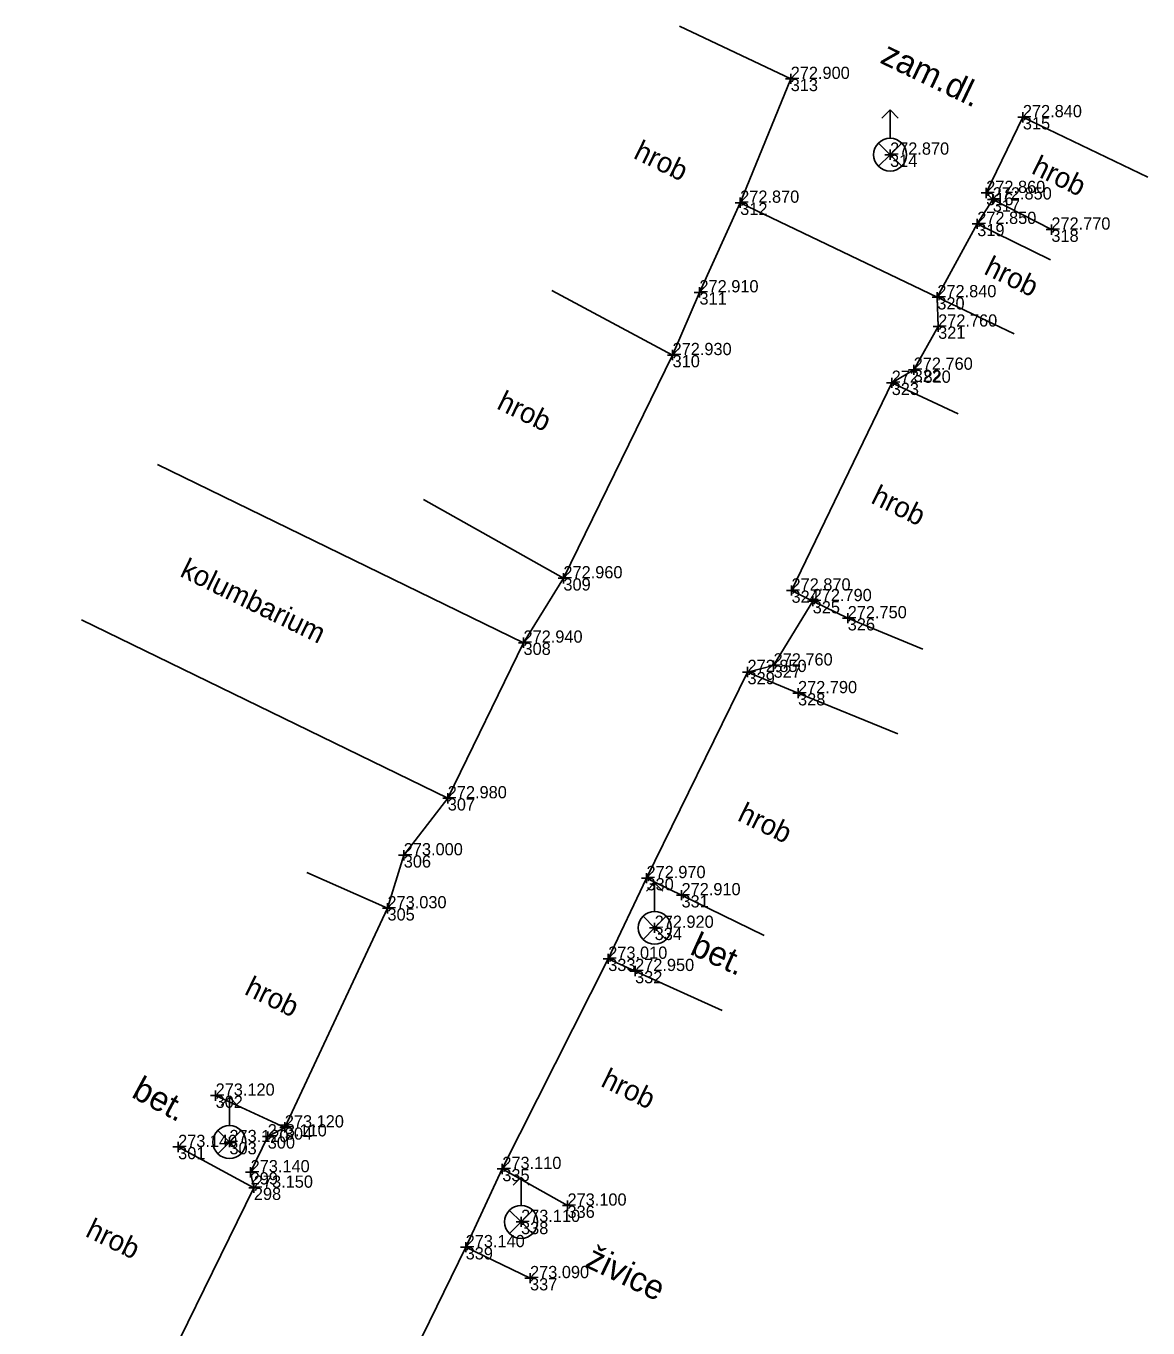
# Model space of a CAD drawing. Extents: x -776606 to -776076, y -974328 to -973875.
# Drawn here: x -776368.79 to -776355.01, y -974179.42 to -974163.44 of the extents above; entities that cross this region are included whole.
import ezdxf

# ---------------------------------------------------------------- set-up
doc = ezdxf.new("R2010")
doc.units = 0
for name, color, linetype in [('Body polohopisu', 7, 'Continuous'), ('Doplňkové značky', 7, 'Continuous'), ('Doplňující texty', 7, 'Continuous'), ('Ploty_opěrné zdi', 7, 'Continuous'), ('Rozhraní ploch', 7, 'Continuous'), ('Výšky bodů', 7, 'Continuous'), ('Čísla bodů', 7, 'Continuous')]:
    doc.layers.add(name, color=color, linetype=linetype)

msp = doc.modelspace()

# ---------------------------------------------------------------- linework, layer by layer
at = {"layer": 'Body polohopisu'}
for p, q in [((-776359.4, -974164.09), (-776359.4, -974164.027)), ((-776359.4, -974164.09), (-776359.463, -974164.09)), ((-776359.4, -974164.09), (-776359.338, -974164.09)), ((-776359.4, -974164.09), (-776359.4, -974164.152)), ((-776356.55, -974164.56), (-776356.55, -974164.498)), ((-776356.55, -974164.56), (-776356.613, -974164.56)), ((-776356.55, -974164.56), (-776356.488, -974164.56)), ((-776356.55, -974164.56), (-776356.55, -974164.623)), ((-776358.18, -974165.02), (-776358.18, -974164.958)), ((-776358.18, -974165.02), (-776358.243, -974165.02)), ((-776358.18, -974165.02), (-776358.118, -974165.02)), ((-776358.18, -974165.02), (-776358.18, -974165.083)), ((-776357, -974165.49), (-776357, -974165.427)), ((-776360.02, -974165.61), (-776360.083, -974165.61)), ((-776360.02, -974165.61), (-776360.02, -974165.547)), ((-776360.02, -974165.61), (-776359.958, -974165.61)), ((-776360.02, -974165.61), (-776360.02, -974165.672)), ((-776357, -974165.49), (-776357.062, -974165.49)), ((-776357, -974165.49), (-776356.938, -974165.49)), ((-776357, -974165.49), (-776357, -974165.552)), ((-776356.92, -974165.57), (-776356.983, -974165.57)), ((-776356.92, -974165.57), (-776356.92, -974165.508)), ((-776356.92, -974165.57), (-776356.858, -974165.57)), ((-776356.92, -974165.57), (-776356.92, -974165.633)), ((-776357.11, -974165.87), (-776357.172, -974165.87)), ((-776357.11, -974165.87), (-776357.11, -974165.807)), ((-776357.11, -974165.87), (-776357.047, -974165.87)), ((-776357.11, -974165.87), (-776357.11, -974165.932)), ((-776356.2, -974165.94), (-776356.263, -974165.94)), ((-776356.2, -974165.94), (-776356.2, -974165.878)), ((-776356.2, -974165.94), (-776356.138, -974165.94)), ((-776356.2, -974165.94), (-776356.2, -974166.003)), ((-776360.52, -974166.71), (-776360.583, -974166.71)), ((-776360.52, -974166.71), (-776360.52, -974166.647)), ((-776360.52, -974166.71), (-776360.458, -974166.71)), ((-776360.52, -974166.71), (-776360.52, -974166.772)), ((-776357.6, -974166.77), (-776357.6, -974166.708)), ((-776357.6, -974166.77), (-776357.662, -974166.77)), ((-776357.6, -974166.77), (-776357.537, -974166.77)), ((-776357.6, -974166.77), (-776357.6, -974166.833)), ((-776357.59, -974167.13), (-776357.59, -974167.068)), ((-776357.59, -974167.13), (-776357.652, -974167.13)), ((-776357.59, -974167.13), (-776357.527, -974167.13)), ((-776357.59, -974167.13), (-776357.59, -974167.193)), ((-776360.85, -974167.48), (-776360.912, -974167.48)), ((-776360.85, -974167.48), (-776360.85, -974167.417)), ((-776360.85, -974167.48), (-776360.787, -974167.48)), ((-776360.85, -974167.48), (-776360.85, -974167.542)), ((-776357.89, -974167.66), (-776357.953, -974167.66)), ((-776357.89, -974167.66), (-776357.89, -974167.598)), ((-776357.89, -974167.66), (-776357.828, -974167.66)), ((-776357.89, -974167.66), (-776357.89, -974167.723)), ((-776358.16, -974167.82), (-776358.223, -974167.82)), ((-776358.16, -974167.82), (-776358.16, -974167.758)), ((-776358.16, -974167.82), (-776358.098, -974167.82)), ((-776358.16, -974167.82), (-776358.16, -974167.883)), ((-776362.19, -974170.22), (-776362.253, -974170.22)), ((-776362.19, -974170.22), (-776362.19, -974170.157)), ((-776362.19, -974170.22), (-776362.128, -974170.22)), ((-776362.19, -974170.22), (-776362.19, -974170.282)), ((-776359.39, -974170.37), (-776359.453, -974170.37)), ((-776359.39, -974170.37), (-776359.39, -974170.307)), ((-776359.39, -974170.37), (-776359.328, -974170.37)), ((-776359.39, -974170.37), (-776359.39, -974170.432)), ((-776359.13, -974170.5), (-776359.193, -974170.5)), ((-776359.13, -974170.5), (-776359.13, -974170.438)), ((-776359.13, -974170.5), (-776359.068, -974170.5)), ((-776359.13, -974170.5), (-776359.13, -974170.562)), ((-776358.7, -974170.71), (-776358.763, -974170.71)), ((-776358.7, -974170.71), (-776358.7, -974170.647)), ((-776358.7, -974170.71), (-776358.638, -974170.71)), ((-776358.7, -974170.71), (-776358.7, -974170.772)), ((-776362.68, -974171.01), (-776362.743, -974171.01)), ((-776362.68, -974171.01), (-776362.68, -974170.948)), ((-776362.68, -974171.01), (-776362.618, -974171.01)), ((-776362.68, -974171.01), (-776362.68, -974171.073)), ((-776359.61, -974171.29), (-776359.61, -974171.228)), ((-776359.93, -974171.37), (-776359.993, -974171.37)), ((-776359.93, -974171.37), (-776359.93, -974171.307)), ((-776359.93, -974171.37), (-776359.868, -974171.37)), ((-776359.93, -974171.37), (-776359.93, -974171.432)), ((-776359.61, -974171.29), (-776359.672, -974171.29)), ((-776359.61, -974171.29), (-776359.547, -974171.29)), ((-776359.61, -974171.29), (-776359.61, -974171.353)), ((-776359.31, -974171.63), (-776359.373, -974171.63)), ((-776359.31, -974171.63), (-776359.31, -974171.568)), ((-776359.31, -974171.63), (-776359.248, -974171.63)), ((-776359.31, -974171.63), (-776359.31, -974171.693)), ((-776363.61, -974172.92), (-776363.672, -974172.92)), ((-776363.61, -974172.92), (-776363.61, -974172.858)), ((-776363.61, -974172.92), (-776363.547, -974172.92)), ((-776363.61, -974172.92), (-776363.61, -974172.983)), ((-776364.15, -974173.62), (-776364.213, -974173.62)), ((-776364.15, -974173.62), (-776364.15, -974173.557)), ((-776364.15, -974173.62), (-776364.088, -974173.62)), ((-776364.15, -974173.62), (-776364.15, -974173.682)), ((-776361.17, -974173.9), (-776361.233, -974173.9)), ((-776361.17, -974173.9), (-776361.17, -974173.838)), ((-776361.17, -974173.9), (-776361.108, -974173.9)), ((-776361.17, -974173.9), (-776361.17, -974173.963)), ((-776360.74, -974174.11), (-776360.802, -974174.11)), ((-776360.74, -974174.11), (-776360.74, -974174.047)), ((-776360.74, -974174.11), (-776360.677, -974174.11)), ((-776360.74, -974174.11), (-776360.74, -974174.172)), ((-776364.35, -974174.27), (-776364.35, -974174.208)), ((-776364.35, -974174.27), (-776364.412, -974174.27)), ((-776364.35, -974174.27), (-776364.287, -974174.27)), ((-776364.35, -974174.27), (-776364.35, -974174.333)), ((-776361.07, -974174.51), (-776361.133, -974174.51)), ((-776361.07, -974174.51), (-776361.07, -974174.448)), ((-776361.07, -974174.51), (-776361.008, -974174.51)), ((-776361.07, -974174.51), (-776361.07, -974174.573)), ((-776361.64, -974174.89), (-776361.703, -974174.89)), ((-776361.64, -974174.89), (-776361.64, -974174.828)), ((-776361.64, -974174.89), (-776361.578, -974174.89)), ((-776361.64, -974174.89), (-776361.64, -974174.953)), ((-776361.31, -974175.04), (-776361.373, -974175.04)), ((-776361.31, -974175.04), (-776361.31, -974174.978)), ((-776361.31, -974175.04), (-776361.248, -974175.04)), ((-776361.31, -974175.04), (-776361.31, -974175.103)), ((-776366.46, -974176.57), (-776366.522, -974176.57)), ((-776366.46, -974176.57), (-776366.46, -974176.508)), ((-776366.46, -974176.57), (-776366.397, -974176.57)), ((-776366.46, -974176.57), (-776366.46, -974176.633)), ((-776365.61, -974176.96), (-776365.672, -974176.96)), ((-776365.61, -974176.96), (-776365.61, -974176.897)), ((-776365.61, -974176.96), (-776365.547, -974176.96)), ((-776365.61, -974176.96), (-776365.61, -974177.022)), ((-776366.92, -974177.2), (-776366.92, -974177.138)), ((-776366.29, -974177.14), (-776366.353, -974177.14)), ((-776366.29, -974177.14), (-776366.29, -974177.078)), ((-776366.29, -974177.14), (-776366.228, -974177.14)), ((-776366.29, -974177.14), (-776366.29, -974177.203)), ((-776365.82, -974177.07), (-776365.883, -974177.07)), ((-776365.82, -974177.07), (-776365.82, -974177.008)), ((-776365.82, -974177.07), (-776365.758, -974177.07)), ((-776365.82, -974177.07), (-776365.82, -974177.133)), ((-776366.92, -974177.2), (-776366.983, -974177.2)), ((-776366.92, -974177.2), (-776366.858, -974177.2)), ((-776366.92, -974177.2), (-776366.92, -974177.263)), ((-776366.03, -974177.51), (-776366.03, -974177.448)), ((-776362.94, -974177.47), (-776362.94, -974177.407)), ((-776366.03, -974177.51), (-776366.093, -974177.51)), ((-776366.03, -974177.51), (-776365.968, -974177.51)), ((-776366.03, -974177.51), (-776366.03, -974177.573)), ((-776362.94, -974177.47), (-776363.003, -974177.47)), ((-776362.94, -974177.47), (-776362.878, -974177.47)), ((-776362.94, -974177.47), (-776362.94, -974177.532)), ((-776365.99, -974177.7), (-776366.052, -974177.7)), ((-776365.99, -974177.7), (-776365.99, -974177.638)), ((-776365.99, -974177.7), (-776365.927, -974177.7)), ((-776365.99, -974177.7), (-776365.99, -974177.763)), ((-776362.14, -974177.92), (-776362.203, -974177.92)), ((-776362.14, -974177.92), (-776362.14, -974177.858)), ((-776362.14, -974177.92), (-776362.078, -974177.92)), ((-776362.14, -974177.92), (-776362.14, -974177.983)), ((-776362.71, -974178.12), (-776362.71, -974178.057)), ((-776362.71, -974178.12), (-776362.772, -974178.12)), ((-776362.71, -974178.12), (-776362.647, -974178.12)), ((-776362.71, -974178.12), (-776362.71, -974178.182)), ((-776363.39, -974178.43), (-776363.39, -974178.368)), ((-776363.39, -974178.43), (-776363.453, -974178.43)), ((-776363.39, -974178.43), (-776363.328, -974178.43)), ((-776363.39, -974178.43), (-776363.39, -974178.493)), ((-776362.6, -974178.81), (-776362.662, -974178.81)), ((-776362.6, -974178.81), (-776362.6, -974178.748)), ((-776362.6, -974178.81), (-776362.537, -974178.81)), ((-776362.6, -974178.81), (-776362.6, -974178.873))]:
    msp.add_line(p, q, dxfattribs=at)
at = {"layer": 'Doplňkové značky'}
for p, q in [((-776358.18, -974164.47), (-776358.28, -974164.57)), ((-776358.18, -974164.818), (-776358.18, -974164.47)), ((-776358.18, -974164.47), (-776358.08, -974164.57)), ((-776358.18, -974165.02), (-776358.322, -974164.878)), ((-776358.18, -974165.02), (-776358.037, -974164.878)), ((-776358.18, -974165.02), (-776358.322, -974165.162)), ((-776358.18, -974165.02), (-776358.18, -974165.02)), ((-776358.18, -974165.02), (-776358.037, -974165.162)), ((-776361.07, -974173.959), (-776361.169, -974174.06)), ((-776361.07, -974174.308), (-776361.07, -974173.959)), ((-776361.07, -974173.959), (-776360.97, -974174.06)), ((-776361.07, -974174.51), (-776361.212, -974174.368)), ((-776361.07, -974174.51), (-776360.927, -974174.368)), ((-776361.07, -974174.51), (-776361.212, -974174.652)), ((-776361.07, -974174.51), (-776361.07, -974174.51)), ((-776361.07, -974174.51), (-776360.927, -974174.652)), ((-776366.29, -974176.59), (-776366.39, -974176.69)), ((-776366.29, -974176.938), (-776366.29, -974176.59)), ((-776366.29, -974176.59), (-776366.19, -974176.69)), ((-776366.29, -974177.14), (-776366.432, -974176.998)), ((-776366.29, -974177.14), (-776366.432, -974177.282)), ((-776366.29, -974177.14), (-776366.147, -974176.998)), ((-776366.29, -974177.14), (-776366.29, -974177.14)), ((-776366.29, -974177.14), (-776366.147, -974177.282)), ((-776362.71, -974177.569), (-776362.809, -974177.67)), ((-776362.71, -974177.918), (-776362.71, -974177.569)), ((-776362.71, -974177.569), (-776362.61, -974177.67)), ((-776362.71, -974178.12), (-776362.852, -974177.978)), ((-776362.71, -974178.12), (-776362.568, -974177.978)), ((-776362.71, -974178.12), (-776362.852, -974178.262)), ((-776362.71, -974178.12), (-776362.71, -974178.12)), ((-776362.71, -974178.12), (-776362.568, -974178.262))]:
    msp.add_line(p, q, dxfattribs=at)
for centre in [(-776358.18, -974165.02), (-776361.07, -974174.51), (-776366.29, -974177.14), (-776362.71, -974178.12)]:
    msp.add_circle(centre, 0.202, dxfattribs=at)
at = {"layer": 'Ploty_opěrné zdi'}
for p, q in [((-776362.68, -974171.01), (-776367.175, -974168.821)), ((-776363.61, -974172.92), (-776368.105, -974170.731))]:
    msp.add_line(p, q, dxfattribs=at)
msp.add_lwpolyline([(-776363.61, -974172.92), (-776362.68, -974171.01)], dxfattribs=at)
at = {"layer": 'Rozhraní ploch'}
for points in [[(-776360.52, -974166.71), (-776360.02, -974165.61), (-776359.4, -974164.09), (-776360.765, -974163.441)], [(-776355.014, -974165.298), (-776356.55, -974164.56), (-776357, -974165.49), (-776356.92, -974165.57), (-776356.2, -974165.94)], [(-776360.02, -974165.61), (-776357.6, -974166.77)], [(-776356.92, -974165.57), (-776357.11, -974165.87)], [(-776356.21, -974166.311), (-776357.11, -974165.87), (-776357.6, -974166.77), (-776356.656, -974167.221)], [(-776363.908, -974169.252), (-776362.19, -974170.22), (-776360.85, -974167.48), (-776362.334, -974166.687)], [(-776360.85, -974167.48), (-776360.52, -974166.71)], [(-776357.6, -974166.77), (-776357.59, -974167.13), (-776357.89, -974167.66), (-776358.16, -974167.82)], [(-776357.344, -974168.199), (-776358.16, -974167.82), (-776359.39, -974170.37), (-776359.13, -974170.5), (-776358.7, -974170.71), (-776357.778, -974171.09)], [(-776362.68, -974171.01), (-776362.19, -974170.22)], [(-776359.13, -974170.5), (-776359.61, -974171.29), (-776359.93, -974171.37)], [(-776358.083, -974172.127), (-776359.31, -974171.63), (-776359.93, -974171.37), (-776361.17, -974173.9), (-776360.74, -974174.11), (-776359.727, -974174.605)], [(-776364.35, -974174.27), (-776364.15, -974173.62), (-776363.61, -974172.92)], [(-776366.46, -974176.57), (-776365.61, -974176.96), (-776364.35, -974174.27), (-776365.339, -974173.832)], [(-776361.17, -974173.9), (-776361.64, -974174.89)], [(-776360.241, -974175.526), (-776361.31, -974175.04), (-776361.64, -974174.89), (-776362.94, -974177.47), (-776362.14, -974177.92)], [(-776365.99, -974177.7), (-776366.03, -974177.51), (-776365.82, -974177.07), (-776365.61, -974176.96)], [(-776368.787, -974179.934), (-776367.41, -974180.6), (-776365.99, -974177.7), (-776366.92, -974177.2)], [(-776362.94, -974177.47), (-776363.39, -974178.43)], [(-776362.6, -974178.81), (-776363.39, -974178.43), (-776364.64, -974180.99), (-776363.416, -974181.576)]]:
    msp.add_lwpolyline(points, dxfattribs=at)

# ---------------------------------------------------------------- texts
at = {"layer": 'Doplňující texty'}
for s, height, rotation, p in [('zam.dl.', 0.3, 334.3898, (-776358.317, -974163.887)), ('hrob', 0.25, 333.9465, (-776361.343, -974165.058)), ('hrob', 0.25, 333.9465, (-776356.458, -974165.244)), ('hrob', 0.25, 333.9465, (-776357.041, -974166.478)), ('hrob', 0.25, 333.9465, (-776363.022, -974168.132)), ('hrob', 0.25, 333.9465, (-776358.428, -974169.289)), ('kolumbarium', 0.25, 334.0346, (-776366.911, -974170.189)), ('hrob', 0.25, 333.9465, (-776360.067, -974173.186)), ('bet.', 0.3, 335.556, (-776360.651, -974174.827)), ('hrob', 0.25, 333.9465, (-776366.119, -974175.319)), ('bet.', 0.3, 331.736, (-776367.506, -974176.582)), ('hrob', 0.25, 333.9465, (-776361.744, -974176.448)), ('hrob', 0.25, 333.9465, (-776368.071, -974178.291)), ('živice', 0.3, 334.3119, (-776361.939, -974178.663))]:
    msp.add_text(s, height=height, rotation=rotation, dxfattribs=at).set_placement(p)
at = {"layer": 'Výšky bodů'}
for s, p in [('272.900', (-776359.4, -974164.09)), ('272.840', (-776356.55, -974164.56)), ('272.870', (-776358.18, -974165.02)), ('272.870', (-776360.02, -974165.61)), ('272.860', (-776357, -974165.49)), ('272.850', (-776356.92, -974165.57)), ('272.850', (-776357.11, -974165.87)), ('272.770', (-776356.2, -974165.94)), ('272.910', (-776360.52, -974166.71)), ('272.840', (-776357.6, -974166.77)), ('272.760', (-776357.59, -974167.13)), ('272.930', (-776360.85, -974167.48)), ('272.760', (-776357.89, -974167.66)), ('272.820', (-776358.16, -974167.82)), ('272.960', (-776362.19, -974170.22)), ('272.870', (-776359.39, -974170.37)), ('272.790', (-776359.13, -974170.5)), ('272.750', (-776358.7, -974170.71)), ('272.940', (-776362.68, -974171.01)), ('272.850', (-776359.93, -974171.37)), ('272.760', (-776359.61, -974171.29)), ('272.790', (-776359.31, -974171.63)), ('272.980', (-776363.61, -974172.92)), ('273.000', (-776364.15, -974173.62)), ('272.970', (-776361.17, -974173.9)), ('272.910', (-776360.74, -974174.11)), ('273.030', (-776364.35, -974174.27)), ('272.920', (-776361.07, -974174.51)), ('273.010', (-776361.64, -974174.89)), ('272.950', (-776361.31, -974175.04)), ('273.120', (-776366.46, -974176.57)), ('273.120', (-776365.61, -974176.96)), ('273.110', (-776365.82, -974177.07)), ('273.140', (-776366.92, -974177.2)), ('273.120', (-776366.29, -974177.14)), ('273.140', (-776366.03, -974177.51)), ('273.110', (-776362.94, -974177.47)), ('273.150', (-776365.99, -974177.7)), ('273.100', (-776362.14, -974177.92)), ('273.110', (-776362.71, -974178.12)), ('273.140', (-776363.39, -974178.43)), ('273.090', (-776362.6, -974178.81))]:
    msp.add_text(s, height=0.15, dxfattribs=at).set_placement(p)
at = {"layer": 'Čísla bodů'}
for s, p in [('313', (-776359.4, -974164.24)), ('315', (-776356.55, -974164.71)), ('314', (-776358.18, -974165.17)), ('312', (-776360.02, -974165.76)), ('316', (-776357, -974165.64)), ('317', (-776356.92, -974165.72)), ('319', (-776357.11, -974166.02)), ('318', (-776356.2, -974166.09)), ('311', (-776360.52, -974166.86)), ('320', (-776357.6, -974166.92)), ('321', (-776357.59, -974167.28)), ('310', (-776360.85, -974167.63)), ('322', (-776357.89, -974167.81)), ('323', (-776358.16, -974167.97)), ('309', (-776362.19, -974170.37)), ('324', (-776359.39, -974170.52)), ('325', (-776359.13, -974170.65)), ('326', (-776358.7, -974170.86)), ('308', (-776362.68, -974171.16)), ('329', (-776359.93, -974171.52)), ('327', (-776359.61, -974171.44)), ('328', (-776359.31, -974171.78)), ('307', (-776363.61, -974173.07)), ('306', (-776364.15, -974173.77)), ('330', (-776361.17, -974174.05)), ('331', (-776360.74, -974174.26)), ('305', (-776364.35, -974174.42)), ('334', (-776361.07, -974174.66)), ('333', (-776361.64, -974175.04)), ('332', (-776361.31, -974175.19)), ('302', (-776366.46, -974176.72)), ('304', (-776365.61, -974177.11)), ('303', (-776366.29, -974177.29)), ('300', (-776365.82, -974177.22)), ('301', (-776366.92, -974177.35)), ('299', (-776366.03, -974177.66)), ('335', (-776362.94, -974177.62)), ('298', (-776365.99, -974177.85)), ('336', (-776362.14, -974178.07)), ('338', (-776362.71, -974178.27)), ('339', (-776363.39, -974178.58)), ('337', (-776362.6, -974178.96))]:
    msp.add_text(s, height=0.15, dxfattribs=at).set_placement(p)

doc.saveas('drawing.dxf')
